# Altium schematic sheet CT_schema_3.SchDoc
size 384 x 228 mm
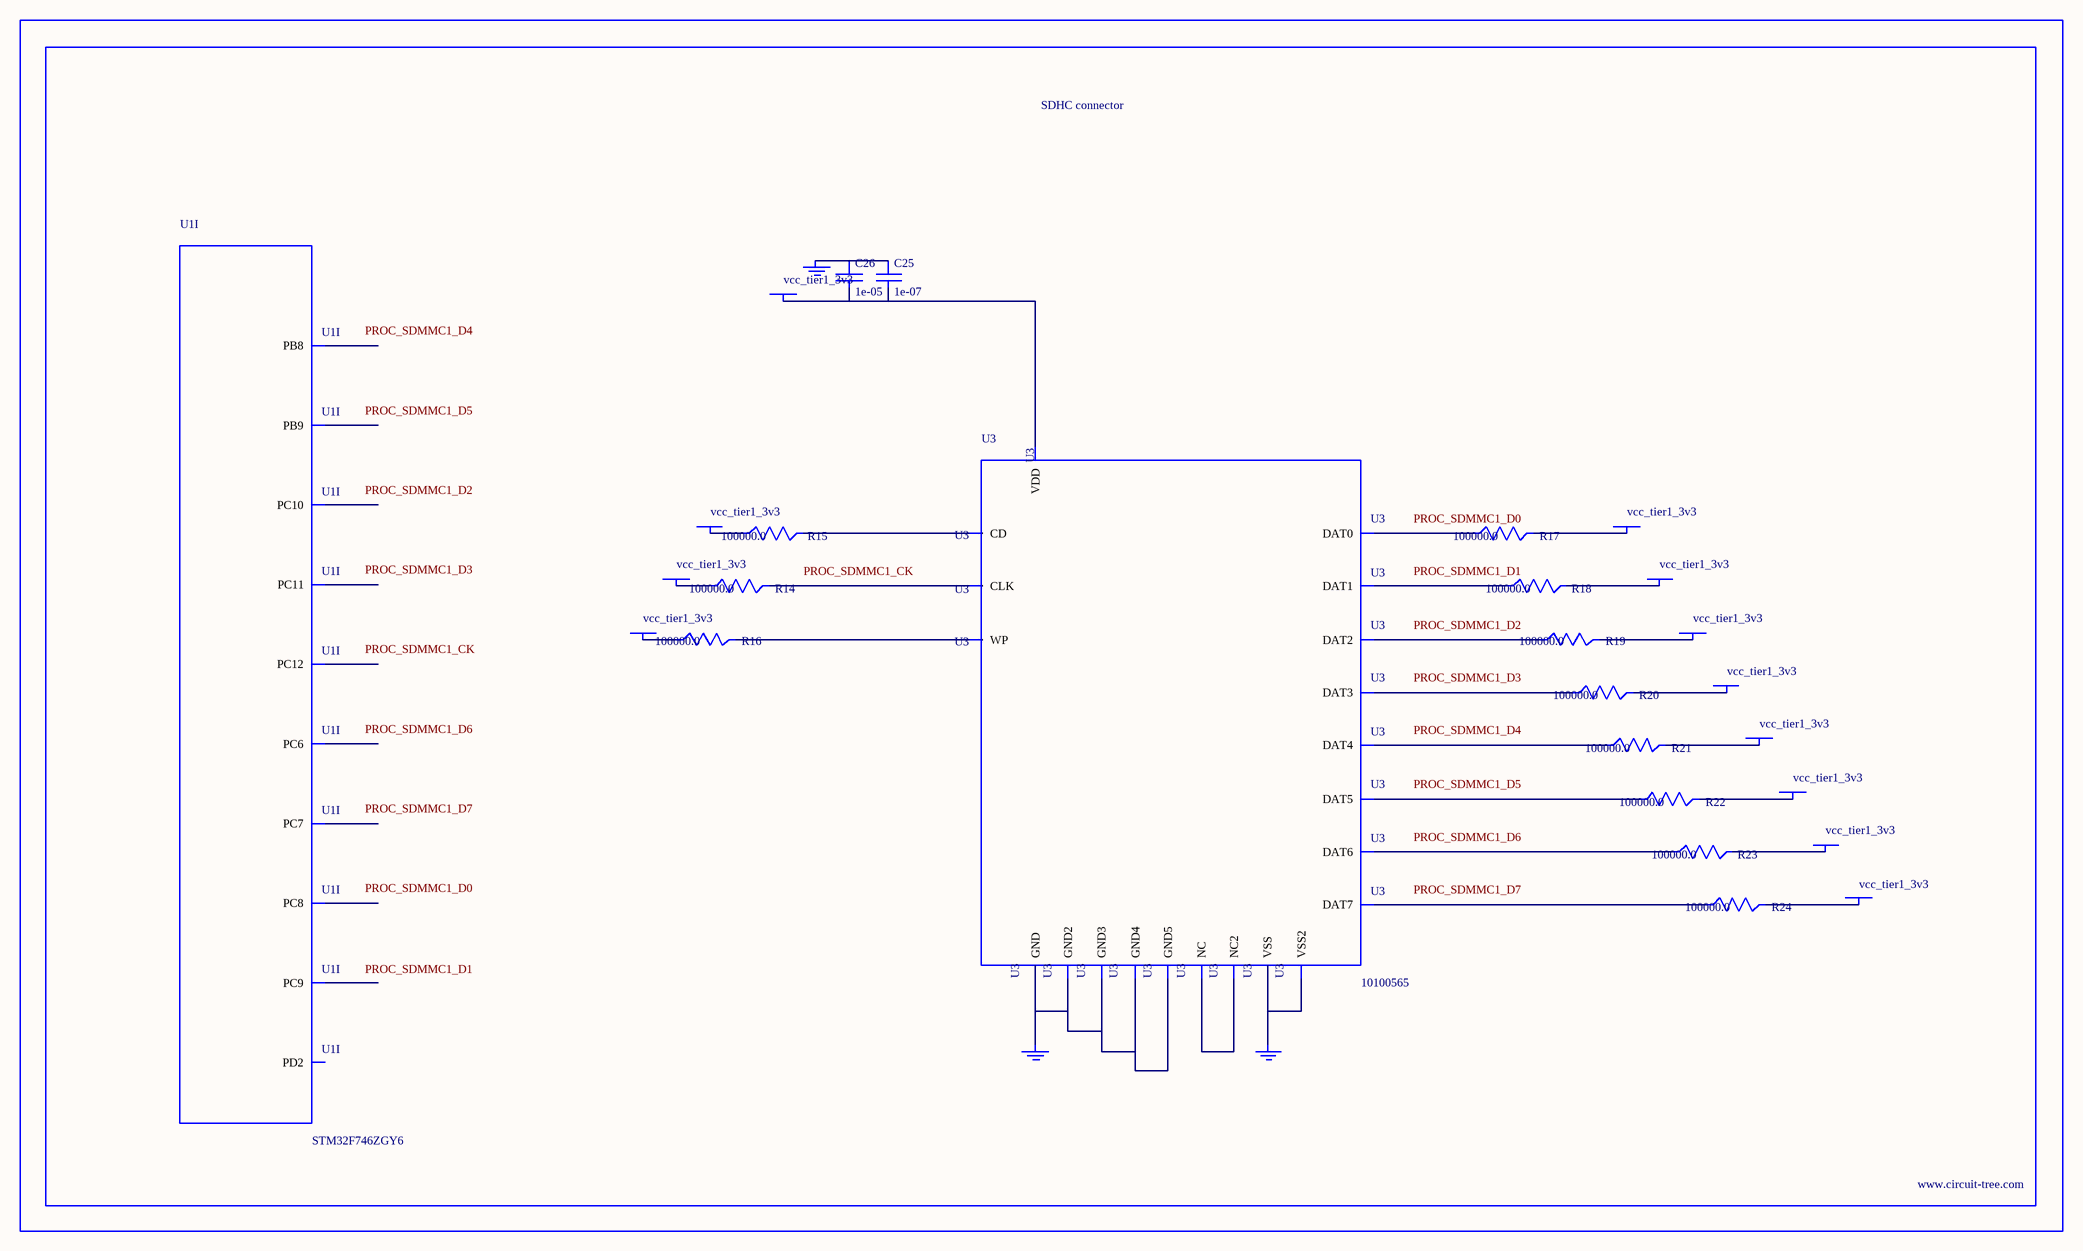
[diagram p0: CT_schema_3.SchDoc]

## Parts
BORDER2  (no value)
C25  1e-07  [C0402]
C26  1e-05  [C0805]
GND_INSTANCE_2_0  (no value)
GND_INSTANCE_2_1  (no value)
GND_INSTANCE_2_2  (no value)
POWER_INSTANCE_2_0  vcc_tier1_3v3
POWER_INSTANCE_2_1  vcc_tier1_3v3
POWER_INSTANCE_2_2  vcc_tier1_3v3
POWER_INSTANCE_2_3  vcc_tier1_3v3
POWER_INSTANCE_2_4  vcc_tier1_3v3
POWER_INSTANCE_2_5  vcc_tier1_3v3
POWER_INSTANCE_2_6  vcc_tier1_3v3
POWER_INSTANCE_2_7  vcc_tier1_3v3
POWER_INSTANCE_2_8  vcc_tier1_3v3
POWER_INSTANCE_2_9  vcc_tier1_3v3
POWER_INSTANCE_2_10  vcc_tier1_3v3
POWER_INSTANCE_2_11  vcc_tier1_3v3
R14  100000.0  [R0603]
R15  100000.0  [R0603]
R16  100000.0  [R0603]
R17  100000.0  [R0603]
R18  100000.0  [R0603]
R19  100000.0  [R0603]
R20  100000.0  [R0603]
R21  100000.0  [R0603]
R22  100000.0  [R0603]
R23  100000.0  [R0603]
R24  100000.0  [R0603]
U1  STM32F746ZGY6  [WLCSP143]  (part I of 13)
U3  10100565  [10100565]

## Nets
NetC25_1: C25.1 C26.1 GND_INSTANCE_2_0.0(GND)
NetC25_2: C25.2 C26.2 POWER_INSTANCE_2_7.0(PWR) U3.9(VDD)
NetGND_INSTANCE_2_1_0: GND_INSTANCE_2_1.0(GND) U3.6(VSS) U3.10(VSS2)
NetGND_INSTANCE_2_2_0: GND_INSTANCE_2_2.0(GND) U3.12(GND) U3.16(GND2) U3.17(GND3) U3.20(GND4) U3.21(GND5)
NetPOWER_INSTANCE_2_0_0: POWER_INSTANCE_2_0.0(PWR) R16.1
NetPOWER_INSTANCE_2_1_0: POWER_INSTANCE_2_1.0(PWR) R15.1
NetPOWER_INSTANCE_2_2_0: POWER_INSTANCE_2_2.0(PWR) R18.2
NetPOWER_INSTANCE_2_3_0: POWER_INSTANCE_2_3.0(PWR) R17.2
NetPOWER_INSTANCE_2_4_0: POWER_INSTANCE_2_4.0(PWR) R24.2
NetPOWER_INSTANCE_2_5_0: POWER_INSTANCE_2_5.0(PWR) R23.2
NetPOWER_INSTANCE_2_6_0: POWER_INSTANCE_2_6.0(PWR) R14.1
NetPOWER_INSTANCE_2_8_0: POWER_INSTANCE_2_8.0(PWR) R22.2
NetPOWER_INSTANCE_2_9_0: POWER_INSTANCE_2_9.0(PWR) R21.2
NetPOWER_INSTANCE_2_10_0: POWER_INSTANCE_2_10.0(PWR) R20.2
NetPOWER_INSTANCE_2_11_0: POWER_INSTANCE_2_11.0(PWR) R19.2
NetR14_2: R14.2 U3.8(CLK)
NetR15_2: R15.2 U3.2(CD)
NetR16_2: R16.2 U3.1(WP)
NetR17_1: R17.1 U3.4(DAT0)
NetR18_1: R18.1 U3.3(DAT1)
NetR19_1: R19.1 U3.15(DAT2)
NetR20_1: R20.1 U3.14(DAT3)
NetR21_1: R21.1 U3.13(DAT4)
NetR22_1: R22.1 U3.11(DAT5)
NetR23_1: R23.1 U3.7(DAT6)
NetR24_1: R24.1 U3.5(DAT7)
NetU3_18: U3.18(NC) U3.19(NC2)

Not connected (* = marked no-connect by the designer): U1 A2(PC10) A3(PD2) A9(PB8) B2(PC11) B9(PB9) C3(PC12) E3(PC9) E4(PC8) F2(PC6) F3(PC7)

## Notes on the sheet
- Labels drawn without touching a wire or pin: PROC_SDMMC1_CK, PROC_SDMMC1_D0, PROC_SDMMC1_D1, PROC_SDMMC1_D2, PROC_SDMMC1_D3, PROC_SDMMC1_D4, PROC_SDMMC1_D5, PROC_SDMMC1_D6, PROC_SDMMC1_D7

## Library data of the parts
BORDER2 = BORDER_PAGE2
C25 = C0402C104K3RACTU
C26 = C0805C106K8RACTU
GND_INSTANCE_2_0-GND_INSTANCE_2_2 = GND
POWER_INSTANCE_2_0-POWER_INSTANCE_2_11 = PWR
R14-R24 = RC0603JR-07100KL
